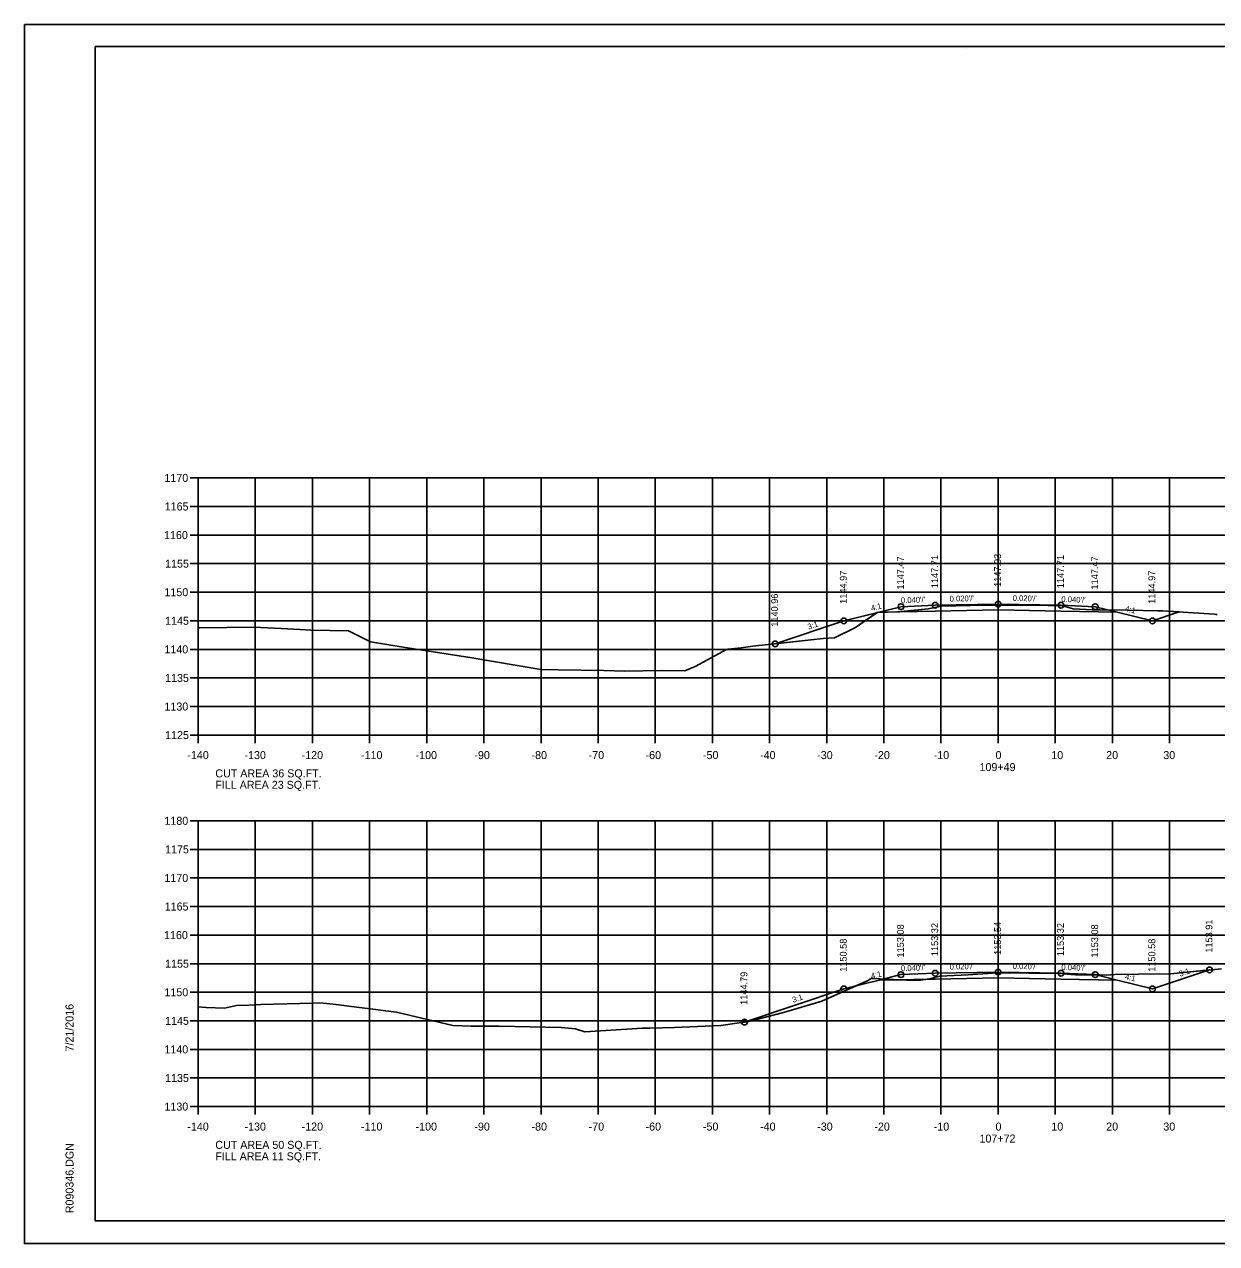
# Model space of a CAD drawing. Extents: x 1368971 to 1374497, y 378717 to 381839.
# Drawn here: x 1370390.1 to 1370598.7, y 381000.4 to 381213.8 of the extents above; entities that cross this region are included whole.
import ezdxf

# ---------------------------------------------------------------- set-up
doc = ezdxf.new("R2010")
doc.units = 0
for name, color, linetype in [('R_Alt Surface', 7, 'Continuous'), ('R_Axis', 7, 'Continuous'), ('R_Axis Annot', 7, 'Continuous'), ('R_Border', 7, 'Continuous'), ('R_Contours', 7, 'Continuous'), ('R_Exist Surface', 7, 'Continuous'), ('R_Fin Surface', 7, 'Continuous'), ('R_Grid', 7, 'Continuous'), ('R_No Plot', 7, 'Continuous'), ('R_Xsect Elev', 7, 'Continuous'), ('R_Xsect Slope', 7, 'Continuous')]:
    doc.layers.add(name, color=color, linetype=linetype)

msp = doc.modelspace()

# ---------------------------------------------------------------- linework, layer by layer
at = {"layer": 'R_Alt Surface'}
for points in [[(1370539.64, 381110.94), (1370549.47, 381111.14), (1370560.47, 381111.36), (1370571.47, 381111.14), (1370581.29, 381110.94)], [(1370539.64, 381046.56), (1370549.47, 381046.75), (1370560.47, 381046.97), (1370571.47, 381046.75), (1370581.29, 381046.56)]]:
    msp.add_lwpolyline(points, dxfattribs=at)
at = {"layer": 'R_Axis'}
for p, q in [((1370419.07, 381134.43), (1370420.47, 381134.43)), ((1370420.47, 381089.43), (1370420.47, 381134.43)), ((1370419.07, 381129.43), (1370420.47, 381129.43)), ((1370419.07, 381124.43), (1370420.47, 381124.43)), ((1370419.07, 381119.43), (1370420.47, 381119.43)), ((1370419.07, 381114.43), (1370420.47, 381114.43)), ((1370419.07, 381109.43), (1370420.47, 381109.43)), ((1370419.07, 381104.43), (1370420.47, 381104.43)), ((1370419.07, 381099.43), (1370420.47, 381099.43)), ((1370419.07, 381094.43), (1370420.47, 381094.43)), ((1370419.07, 381089.43), (1370420.47, 381089.43)), ((1370420.47, 381089.43), (1370700.47, 381089.43)), ((1370420.47, 381088.03), (1370420.47, 381089.43)), ((1370430.47, 381088.03), (1370430.47, 381089.43)), ((1370440.47, 381088.03), (1370440.47, 381089.43)), ((1370450.47, 381088.03), (1370450.47, 381089.43)), ((1370460.47, 381088.03), (1370460.47, 381089.43)), ((1370470.47, 381088.03), (1370470.47, 381089.43)), ((1370480.47, 381088.03), (1370480.47, 381089.43)), ((1370490.47, 381088.03), (1370490.47, 381089.43)), ((1370500.47, 381088.03), (1370500.47, 381089.43)), ((1370510.47, 381088.03), (1370510.47, 381089.43)), ((1370520.47, 381088.03), (1370520.47, 381089.43)), ((1370530.47, 381088.03), (1370530.47, 381089.43)), ((1370540.47, 381088.03), (1370540.47, 381089.43)), ((1370550.47, 381088.03), (1370550.47, 381089.43)), ((1370560.47, 381088.03), (1370560.47, 381089.43)), ((1370570.47, 381088.03), (1370570.47, 381089.43)), ((1370580.47, 381088.03), (1370580.47, 381089.43)), ((1370590.47, 381088.03), (1370590.47, 381089.43)), ((1370419.07, 381074.43), (1370420.47, 381074.43)), ((1370420.47, 381024.43), (1370420.47, 381074.43)), ((1370419.07, 381069.43), (1370420.47, 381069.43)), ((1370419.07, 381064.43), (1370420.47, 381064.43)), ((1370419.07, 381059.43), (1370420.47, 381059.43)), ((1370419.07, 381054.43), (1370420.47, 381054.43)), ((1370419.07, 381049.43), (1370420.47, 381049.43)), ((1370419.07, 381044.43), (1370420.47, 381044.43)), ((1370419.07, 381039.43), (1370420.47, 381039.43)), ((1370419.07, 381034.43), (1370420.47, 381034.43)), ((1370419.07, 381029.43), (1370420.47, 381029.43)), ((1370419.07, 381024.43), (1370420.47, 381024.43)), ((1370420.47, 381024.43), (1370700.47, 381024.43)), ((1370420.47, 381023.03), (1370420.47, 381024.43)), ((1370430.47, 381023.03), (1370430.47, 381024.43)), ((1370440.47, 381023.03), (1370440.47, 381024.43)), ((1370450.47, 381023.03), (1370450.47, 381024.43)), ((1370460.47, 381023.03), (1370460.47, 381024.43)), ((1370470.47, 381023.03), (1370470.47, 381024.43)), ((1370480.47, 381023.03), (1370480.47, 381024.43)), ((1370490.47, 381023.03), (1370490.47, 381024.43)), ((1370500.47, 381023.03), (1370500.47, 381024.43)), ((1370510.47, 381023.03), (1370510.47, 381024.43)), ((1370520.47, 381023.03), (1370520.47, 381024.43)), ((1370530.47, 381023.03), (1370530.47, 381024.43)), ((1370540.47, 381023.03), (1370540.47, 381024.43)), ((1370550.47, 381023.03), (1370550.47, 381024.43)), ((1370560.47, 381023.03), (1370560.47, 381024.43)), ((1370570.47, 381023.03), (1370570.47, 381024.43)), ((1370580.47, 381023.03), (1370580.47, 381024.43)), ((1370590.47, 381023.03), (1370590.47, 381024.43))]:
    msp.add_line(p, q, dxfattribs=at)
at = {"layer": 'R_Border'}
for p, q in [((1370402.47, 381209.89), (1370718.65, 381209.89)), ((1370402.47, 381004.43), (1370402.47, 381209.89)), ((1370554.99, 381209.63), (1370554.99, 381209.63)), ((1370554.99, 381209.63), (1370554.99, 381209.63)), ((1370402.47, 381004.43), (1370402.47, 381004.43)), ((1370718.65, 381004.43), (1370402.47, 381004.43))]:
    msp.add_line(p, q, dxfattribs=at)
at = {"layer": 'R_Contours'}
for points in [[(1370521.45, 381105.39), (1370529.87, 381106.33), (1370531.81, 381106.44), (1370535.5, 381108.25), (1370539.22, 381110.84), (1370533.47, 381109.4)], [(1370539.22, 381110.84), (1370539.26, 381110.87), (1370539.35, 381110.87)], [(1370539.35, 381110.87), (1370542.86, 381110.98), (1370543.23, 381111.01), (1370539.64, 381110.94)], [(1370543.23, 381111.01), (1370548.21, 381111.51), (1370549.99, 381111.87), (1370550.51, 381111.97), (1370558.14, 381112.14), (1370560.99, 381112.19), (1370569.21, 381112.1), (1370571.76, 381112.05), (1370572.35, 381111.87), (1370573.59, 381111.5), (1370576.9, 381111.36), (1370577.59, 381111.34), (1370578.35, 381111.34), (1370583.13, 381111.31), (1370588.39, 381111.17), (1370588.9, 381111.18), (1370589.26, 381111.17), (1370592.18, 381110.97), (1370587.47, 381109.4), (1370581.29, 381110.94), (1370571.47, 381111.14), (1370560.47, 381111.36), (1370549.47, 381111.14)], [(1370535.58, 381045.54), (1370537.73, 381046.5), (1370538.03, 381046.73), (1370538.31, 381046.82), (1370538.51, 381046.85), (1370538.54, 381046.86), (1370538.6, 381046.84), (1370543.21, 381046.63), (1370539.64, 381046.56)], [(1370543.21, 381046.63), (1370545.64, 381046.51), (1370546.89, 381046.56), (1370548.07, 381046.72)], [(1370548.07, 381046.72), (1370548.18, 381046.74), (1370550.29, 381047.26), (1370555.22, 381047.5), (1370560.35, 381047.81), (1370565.86, 381047.77), (1370571.2, 381047.71), (1370573.17, 381047.52), (1370574.03, 381047.48), (1370578.27, 381047.5), (1370579.47, 381047.43), (1370580.88, 381047.51), (1370585.02, 381047.59), (1370590.67, 381047.66), (1370592.3, 381047.85), (1370597.47, 381048.35), (1370587.47, 381045.01), (1370581.29, 381046.56), (1370571.47, 381046.75), (1370560.47, 381046.97), (1370549.47, 381046.75)], [(1370516.08, 381039.22), (1370517.06, 381039.35), (1370522.92, 381040.88), (1370529.63, 381042.89), (1370535.58, 381045.54), (1370533.47, 381045.01)]]:
    msp.add_lwpolyline(points, close=True, dxfattribs=at)
at = {"layer": 'R_Exist Surface'}
for points in [[(1370420.47, 381108.12), (1370420.54, 381108.17), (1370420.78, 381108.17), (1370430.21, 381108.33), (1370435.01, 381108.07), (1370438.27, 381107.9), (1370440.21, 381107.78), (1370446.8, 381107.67), (1370450.42, 381105.88), (1370450.63, 381105.73), (1370456.32, 381104.8), (1370468.03, 381103), (1370480.79, 381100.87), (1370481.47, 381100.88), (1370483.47, 381100.84), (1370491.45, 381100.75), (1370495.12, 381100.6), (1370501.52, 381100.74), (1370505.65, 381100.7), (1370507.47, 381101.41), (1370512.91, 381104.42), (1370513.18, 381104.47), (1370515.49, 381104.72), (1370517.52, 381104.96), (1370529.87, 381106.33), (1370531.81, 381106.44), (1370535.5, 381108.25), (1370539.26, 381110.87), (1370542.86, 381110.98), (1370548.21, 381111.51), (1370549.99, 381111.87), (1370550.51, 381111.97), (1370558.14, 381112.14), (1370560.99, 381112.19), (1370569.21, 381112.1), (1370571.76, 381112.05), (1370572.35, 381111.87), (1370573.59, 381111.5), (1370576.9, 381111.36), (1370577.59, 381111.34), (1370578.35, 381111.34), (1370583.13, 381111.31), (1370588.39, 381111.17), (1370588.9, 381111.18), (1370589.26, 381111.17), (1370594.65, 381110.8), (1370598.35, 381110.56), (1370598.59, 381110.54), (1370598.83, 381110.53)], [(1370420.47, 381041.87), (1370421.89, 381041.77), (1370425.06, 381041.65), (1370427.17, 381042.11), (1370429.35, 381042.15), (1370431.41, 381042.26), (1370440.55, 381042.55), (1370441.77, 381042.58), (1370444.11, 381042.37), (1370455.19, 381040.96), (1370465.02, 381038.64), (1370468.26, 381038.49), (1370468.57, 381038.51), (1370470.77, 381038.49), (1370473.15, 381038.47), (1370483.97, 381038.26), (1370486.48, 381038.01), (1370488.16, 381037.49), (1370498.22, 381038.17), (1370499.52, 381038.14), (1370503.82, 381038.27), (1370507.86, 381038.43), (1370511.95, 381038.62), (1370514.76, 381039.04), (1370517.06, 381039.35), (1370522.92, 381040.88), (1370529.63, 381042.89), (1370537.73, 381046.5), (1370538.03, 381046.73), (1370538.31, 381046.82), (1370538.51, 381046.85), (1370538.54, 381046.86), (1370538.6, 381046.84), (1370545.64, 381046.51), (1370546.89, 381046.56), (1370548.18, 381046.74), (1370550.29, 381047.26), (1370555.22, 381047.5), (1370560.35, 381047.81), (1370565.86, 381047.77), (1370571.2, 381047.71), (1370573.17, 381047.52), (1370574.03, 381047.48), (1370578.27, 381047.5), (1370579.47, 381047.43), (1370580.88, 381047.51), (1370585.02, 381047.59), (1370590.67, 381047.66), (1370592.3, 381047.85), (1370599.58, 381048.55)]]:
    msp.add_lwpolyline(points, dxfattribs=at)
at = {"layer": 'R_Fin Surface'}
for points in [[(1370521.45, 381105.39), (1370533.47, 381109.4), (1370539.64, 381110.94), (1370543.47, 381111.9), (1370549.47, 381112.14), (1370560.47, 381112.36), (1370571.47, 381112.14), (1370577.47, 381111.9), (1370581.29, 381110.94), (1370587.47, 381109.4), (1370592.18, 381110.97)], [(1370516.08, 381039.22), (1370533.47, 381045.01), (1370539.64, 381046.56), (1370543.47, 381047.51), (1370549.47, 381047.75), (1370560.47, 381047.97), (1370571.47, 381047.75), (1370577.47, 381047.51), (1370581.29, 381046.56), (1370587.47, 381045.01), (1370597.47, 381048.35)]]:
    msp.add_lwpolyline(points, dxfattribs=at)
at = {"layer": 'R_Grid'}
for p, q in [((1370420.47, 381134.43), (1370700.47, 381134.43)), ((1370420.47, 381089.43), (1370420.47, 381134.43)), ((1370430.47, 381089.43), (1370430.47, 381134.43)), ((1370440.47, 381089.43), (1370440.47, 381134.43)), ((1370450.47, 381089.43), (1370450.47, 381134.43)), ((1370460.47, 381089.43), (1370460.47, 381134.43)), ((1370470.47, 381089.43), (1370470.47, 381134.43)), ((1370480.47, 381089.43), (1370480.47, 381134.43)), ((1370490.47, 381089.43), (1370490.47, 381134.43)), ((1370500.47, 381089.43), (1370500.47, 381134.43)), ((1370510.47, 381089.43), (1370510.47, 381134.43)), ((1370520.47, 381089.43), (1370520.47, 381134.43)), ((1370530.47, 381089.43), (1370530.47, 381134.43)), ((1370540.47, 381089.43), (1370540.47, 381134.43)), ((1370550.47, 381089.43), (1370550.47, 381134.43)), ((1370560.47, 381089.43), (1370560.47, 381134.43)), ((1370570.47, 381089.43), (1370570.47, 381134.43)), ((1370580.47, 381089.43), (1370580.47, 381134.43)), ((1370590.47, 381089.43), (1370590.47, 381134.43)), ((1370420.47, 381129.43), (1370700.47, 381129.43)), ((1370420.47, 381124.43), (1370700.47, 381124.43)), ((1370420.47, 381119.43), (1370700.47, 381119.43)), ((1370420.47, 381114.43), (1370700.47, 381114.43)), ((1370420.47, 381109.43), (1370700.47, 381109.43)), ((1370420.47, 381104.43), (1370700.47, 381104.43)), ((1370420.47, 381099.43), (1370700.47, 381099.43)), ((1370420.47, 381094.43), (1370700.47, 381094.43)), ((1370420.47, 381089.43), (1370700.47, 381089.43)), ((1370420.47, 381074.43), (1370700.47, 381074.43)), ((1370420.47, 381024.43), (1370420.47, 381074.43)), ((1370430.47, 381024.43), (1370430.47, 381074.43)), ((1370440.47, 381024.43), (1370440.47, 381074.43)), ((1370450.47, 381024.43), (1370450.47, 381074.43)), ((1370460.47, 381024.43), (1370460.47, 381074.43)), ((1370470.47, 381024.43), (1370470.47, 381074.43)), ((1370480.47, 381024.43), (1370480.47, 381074.43)), ((1370490.47, 381024.43), (1370490.47, 381074.43)), ((1370500.47, 381024.43), (1370500.47, 381074.43)), ((1370510.47, 381024.43), (1370510.47, 381074.43)), ((1370520.47, 381024.43), (1370520.47, 381074.43)), ((1370530.47, 381024.43), (1370530.47, 381074.43)), ((1370540.47, 381024.43), (1370540.47, 381074.43)), ((1370550.47, 381024.43), (1370550.47, 381074.43)), ((1370560.47, 381024.43), (1370560.47, 381074.43)), ((1370570.47, 381024.43), (1370570.47, 381074.43)), ((1370580.47, 381024.43), (1370580.47, 381074.43)), ((1370590.47, 381024.43), (1370590.47, 381074.43)), ((1370420.47, 381069.43), (1370700.47, 381069.43)), ((1370420.47, 381064.43), (1370700.47, 381064.43)), ((1370420.47, 381059.43), (1370700.47, 381059.43)), ((1370420.47, 381054.43), (1370700.47, 381054.43)), ((1370420.47, 381049.43), (1370700.47, 381049.43)), ((1370420.47, 381044.43), (1370700.47, 381044.43)), ((1370420.47, 381039.43), (1370700.47, 381039.43)), ((1370420.47, 381034.43), (1370700.47, 381034.43)), ((1370420.47, 381029.43), (1370700.47, 381029.43)), ((1370420.47, 381024.43), (1370700.47, 381024.43))]:
    msp.add_line(p, q, dxfattribs=at)
at = {"layer": 'R_No Plot'}
for p, q in [((1370390.07, 381213.79), (1370723.4, 381213.79)), ((1370390.07, 381000.45), (1370723.4, 381000.45))]:
    msp.add_line(p, q, dxfattribs=at)
for points in [[(1370390.06, 381213.79), (1370723.4, 381213.79), (1370723.4, 381000.45), (1370390.06, 381000.45)], [(1370636.39, 381209.89), (1370636.39, 381200.01), (1370672.12, 381200.01), (1370672.12, 381197.09), (1370695.32, 381197.09), (1370695.32, 381173.88), (1370718.65, 381173.88), (1370718.65, 381004.43), (1370402.47, 381004.43), (1370402.47, 381209.89)]]:
    msp.add_lwpolyline(points, close=True, dxfattribs=at)
for centre in [(1370560.47, 381112.36), (1370543.47, 381111.9), (1370549.47, 381112.14), (1370571.47, 381112.14), (1370577.47, 381111.9), (1370533.47, 381109.4), (1370587.47, 381109.4), (1370521.45, 381105.39), (1370597.47, 381048.35), (1370543.47, 381047.51), (1370549.47, 381047.75), (1370560.47, 381047.97), (1370571.47, 381047.75), (1370577.47, 381047.51), (1370533.47, 381045.01), (1370587.47, 381045.01), (1370516.08, 381039.22)]:
    msp.add_circle(centre, 0.5, dxfattribs=at)

# ---------------------------------------------------------------- texts
at = {"layer": 'R_Axis'}
for p in [(1370420.47, 381089.43), (1370420.47, 381024.43)]:
    msp.add_text('-', height=0.0001, dxfattribs=at).set_placement(p)
at = {"layer": 'R_Axis Annot'}
for s, p in [('1170', (1370414.57, 381133.73)), ('1165', (1370414.62, 381128.73)), ('1160', (1370414.5, 381123.73)), ('1155', (1370414.69, 381118.73)), ('1150', (1370414.57, 381113.73)), ('1145', (1370414.69, 381108.73)), ('1140', (1370414.57, 381103.73)), ('1135', (1370414.69, 381098.73)), ('1130', (1370414.57, 381093.73)), ('1125', (1370414.69, 381088.73)), ('-140', (1370418.58, 381085.23)), ('-130', (1370428.58, 381085.23)), ('-120', (1370438.58, 381085.23)), ('-110', (1370448.97, 381085.23)), ('-100', (1370458.52, 381085.23)), ('-90', (1370468.81, 381085.23)), ('-80', (1370478.81, 381085.23)), ('-70', (1370488.81, 381085.23)), ('-60', (1370498.77, 381085.23)), ('-50', (1370508.81, 381085.23)), ('-40', (1370518.81, 381085.23)), ('-30', (1370528.81, 381085.23)), ('-20', (1370538.81, 381085.23)), ('-10', (1370549.2, 381085.23)), ('0', (1370560.01, 381085.23)), ('10', (1370569.78, 381085.23)), ('20', (1370579.38, 381085.23)), ('30', (1370589.38, 381085.23)), ('CUT AREA 36 SQ.FT.', (1370423.47, 381082.03)), ('109+49', (1370557.21, 381083.13)), ('FILL AREA 23 SQ.FT.', (1370423.47, 381080.03)), ('1180', (1370414.57, 381073.73)), ('1175', (1370414.69, 381068.73)), ('1170', (1370414.57, 381063.73)), ('1165', (1370414.62, 381058.73)), ('1160', (1370414.5, 381053.73)), ('1155', (1370414.69, 381048.73)), ('1150', (1370414.57, 381043.73)), ('1145', (1370414.69, 381038.73)), ('1140', (1370414.57, 381033.73)), ('1135', (1370414.69, 381028.73)), ('1130', (1370414.57, 381023.73)), ('-140', (1370418.58, 381020.23)), ('-130', (1370428.58, 381020.23)), ('-120', (1370438.58, 381020.23)), ('-110', (1370448.97, 381020.23)), ('-100', (1370458.52, 381020.23)), ('-90', (1370468.81, 381020.23)), ('-80', (1370478.81, 381020.23)), ('-70', (1370488.81, 381020.23)), ('-60', (1370498.77, 381020.23)), ('-50', (1370508.81, 381020.23)), ('-40', (1370518.81, 381020.23)), ('-30', (1370528.81, 381020.23)), ('-20', (1370538.81, 381020.23)), ('-10', (1370549.2, 381020.23)), ('0', (1370560.01, 381020.23)), ('10', (1370569.78, 381020.23)), ('20', (1370579.38, 381020.23)), ('30', (1370589.38, 381020.23)), ('107+72', (1370557.21, 381018.13)), ('CUT AREA 50 SQ.FT.', (1370423.47, 381017.03)), ('FILL AREA 11 SQ.FT.', (1370423.47, 381015.03))]:
    msp.add_text(s, height=1.4, dxfattribs=at).set_placement(p)
at = {"layer": 'R_Border'}
for s, p in [('7/21/2016', (1370398.66, 381034.07)), ('R090346.DGN', (1370398.66, 381005.76))]:
    msp.add_text(s, height=1.4, rotation=90, dxfattribs=at).set_placement(p)
at = {"layer": 'R_Xsect Elev'}
for s, p in [('1147.47', (1370543.97, 381114.9)), ('1147.71', (1370549.97, 381115.14)), ('1147.93', (1370560.97, 381115.36)), ('1147.71', (1370571.97, 381115.14)), ('1147.47', (1370577.97, 381114.9)), ('1144.97', (1370533.97, 381112.4)), ('1144.97', (1370587.97, 381112.4)), ('1140.96', (1370521.95, 381108.39)), ('1153.08', (1370543.97, 381050.51)), ('1153.32', (1370549.97, 381050.75)), ('1153.54', (1370560.97, 381050.97)), ('1153.32', (1370571.97, 381050.75)), ('1153.08', (1370577.97, 381050.51)), ('1153.91', (1370597.97, 381051.35)), ('1150.58', (1370533.97, 381048.01)), ('1150.58', (1370587.97, 381048.01)), ('1144.79', (1370516.58, 381042.22))]:
    msp.add_text(s, height=1.2, rotation=90, dxfattribs=at).set_placement(p)
at = {"layer": 'R_Xsect Slope'}
for s, rotation, p in [("0.040'/'", 2.2906, (1370543.48, 381112.5)), ("0.020'/'", 1.1458, (1370551.99, 381112.79)), ("0.020'/'", 358.8542, (1370563.01, 381112.91)), ("0.040'/'", 357.7094, (1370571.52, 381112.74)), ('4:1', 14.0362, (1370538.34, 381111.13)), ('4:1', 345.9638, (1370582.59, 381111.13)), ('3:1', 18.4349, (1370527.3, 381107.87)), ("0.040'/'", 2.2906, (1370543.48, 381048.11)), ("0.020'/'", 1.1458, (1370551.99, 381048.4)), ("0.020'/'", 358.8542, (1370563.01, 381048.52)), ("0.040'/'", 357.7094, (1370571.52, 381048.35)), ('4:1', 14.0362, (1370538.34, 381046.75)), ('4:1', 345.9638, (1370582.59, 381046.75)), ('3:1', 18.4349, (1370592.31, 381047.15)), ('3:1', 18.4349, (1370524.62, 381042.59))]:
    msp.add_text(s, height=1, rotation=rotation, dxfattribs=at).set_placement(p)

doc.saveas('drawing.dxf')
